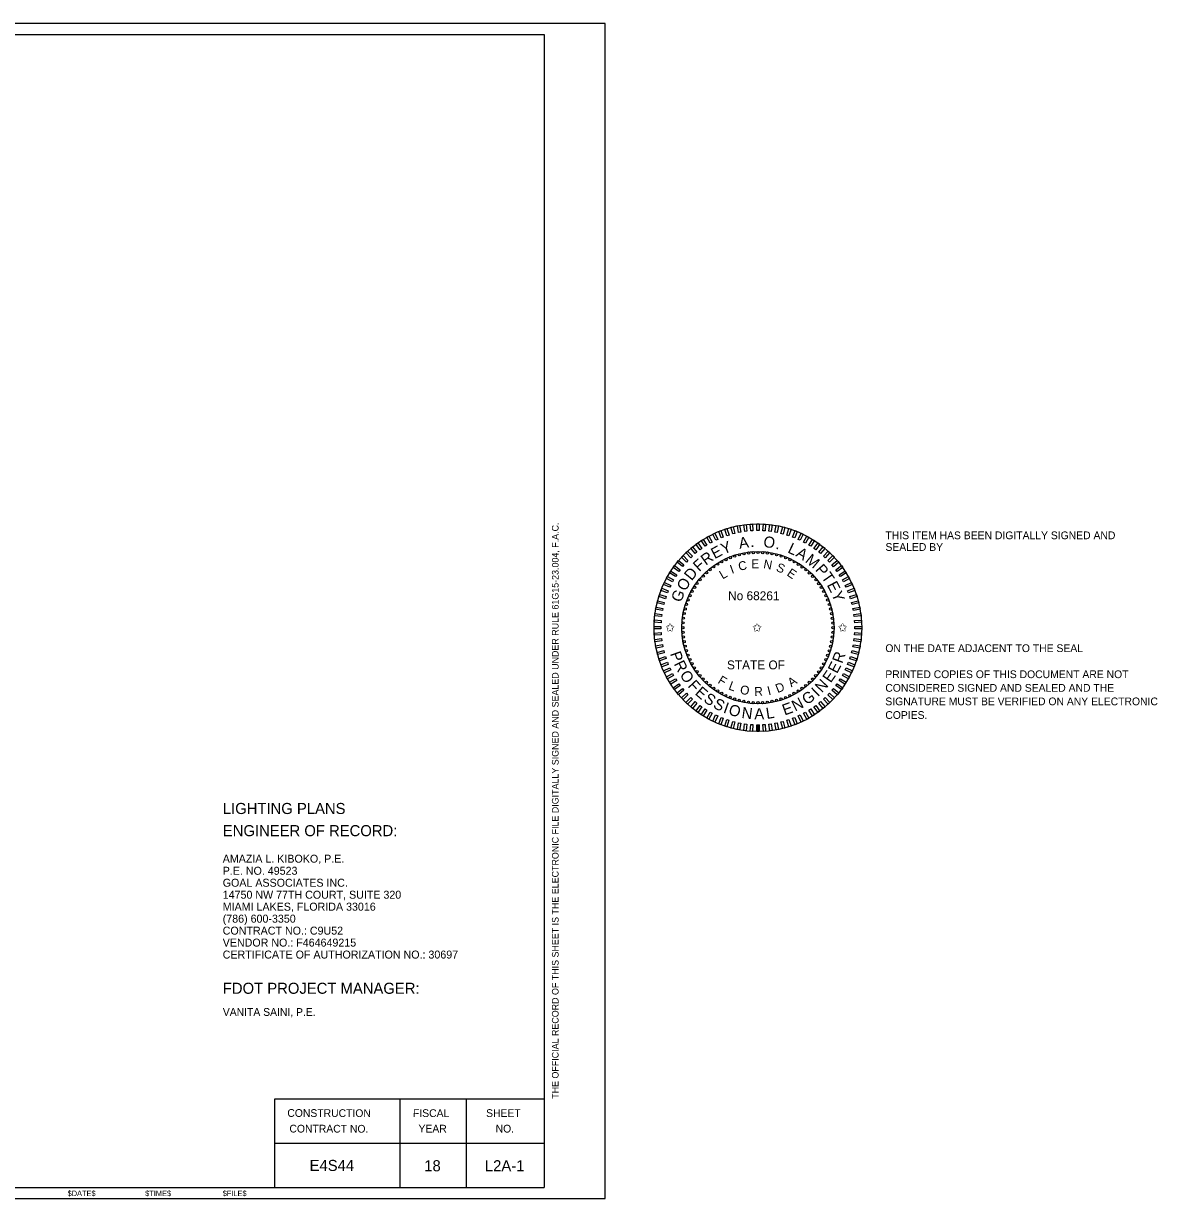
# Model space of a CAD drawing. Extents: x -820.2 to -798.7, y -2201.1 to -2188.5.
# Drawn here: x -808.98 to -798.74, y -2199.12 to -2188.52 of the extents above; entities that cross this region are included whole.
import ezdxf

# ---------------------------------------------------------------- set-up
doc = ezdxf.new("R2010")
doc.units = 0
for name, color, linetype in [('ActivePointCell_dp', 7, 'Continuous'), ('Logo_dp', 7, 'Continuous'), ('NonPlottingEle_dp', 7, 'Continuous'), ('PlotBorder_dp', 7, 'Continuous'), ('SheetBorder_dp', 7, 'Continuous'), ('SheetLines_dp', 7, 'Continuous'), ('TextLabel', 7, 'Continuous'), ('TextMinor', 7, 'Continuous'), ('TextMisc', 7, 'Continuous'), ('TextNotes', 7, 'Continuous'), ('TextShtNo', 7, 'Continuous')]:
    doc.layers.add(name, color=color, linetype=linetype)

msp = doc.modelspace()

# ---------------------------------------------------------------- linework, layer by layer
at = {"layer": 'ActivePointCell_dp'}
msp.add_line((-804.277, -2188.624), (-804.277, -2188.624), dxfattribs=at)
at = {"layer": 'Logo_dp'}
for p, q in [((-802.358, -2194.911), (-802.358, -2194.849)), ((-802.348, -2194.911), (-802.348, -2194.849)), ((-802.338, -2194.911), (-802.338, -2194.848))]:
    msp.add_line(p, q, dxfattribs=at)
for points in [[(-802.711, -2193.177), (-802.729, -2193.186), (-802.756, -2193.13), (-802.738, -2193.121)], [(-802.66, -2193.156), (-802.679, -2193.164), (-802.702, -2193.106), (-802.683, -2193.098)], [(-802.608, -2193.138), (-802.628, -2193.144), (-802.647, -2193.085), (-802.628, -2193.079)], [(-802.556, -2193.123), (-802.575, -2193.128), (-802.591, -2193.068), (-802.571, -2193.063)], [(-802.502, -2193.112), (-802.522, -2193.116), (-802.533, -2193.055), (-802.513, -2193.051)], [(-802.447, -2193.104), (-802.467, -2193.107), (-802.475, -2193.045), (-802.455, -2193.042)], [(-802.393, -2193.1), (-802.413, -2193.101), (-802.417, -2193.039), (-802.396, -2193.037)], [(-802.338, -2193.098), (-802.358, -2193.098), (-802.358, -2193.036), (-802.338, -2193.036)], [(-802.283, -2193.101), (-802.303, -2193.1), (-802.299, -2193.037), (-802.279, -2193.039)], [(-802.228, -2193.107), (-802.248, -2193.104), (-802.24, -2193.042), (-802.22, -2193.045)], [(-802.174, -2193.116), (-802.194, -2193.112), (-802.182, -2193.051), (-802.162, -2193.055)], [(-802.12, -2193.129), (-802.14, -2193.124), (-802.124, -2193.063), (-802.105, -2193.068)], [(-802.068, -2193.144), (-802.087, -2193.138), (-802.068, -2193.079), (-802.048, -2193.085)], [(-802.016, -2193.164), (-802.035, -2193.156), (-802.012, -2193.098), (-801.993, -2193.106)], [(-801.966, -2193.186), (-801.984, -2193.178), (-801.958, -2193.121), (-801.939, -2193.13)], [(-802.898, -2193.293), (-802.913, -2193.306), (-802.953, -2193.258), (-802.937, -2193.245)], [(-802.854, -2193.26), (-802.87, -2193.271), (-802.907, -2193.221), (-802.891, -2193.209)], [(-802.808, -2193.229), (-802.825, -2193.24), (-802.859, -2193.187), (-802.841, -2193.177)], [(-802.76, -2193.202), (-802.778, -2193.212), (-802.808, -2193.157), (-802.79, -2193.147)], [(-801.917, -2193.212), (-801.935, -2193.202), (-801.905, -2193.147), (-801.887, -2193.157)], [(-801.87, -2193.24), (-801.887, -2193.229), (-801.854, -2193.177), (-801.837, -2193.187)], [(-801.825, -2193.272), (-801.842, -2193.26), (-801.805, -2193.209), (-801.788, -2193.221)], [(-801.782, -2193.306), (-801.798, -2193.293), (-801.758, -2193.245), (-801.742, -2193.258)], [(-802.979, -2193.367), (-802.992, -2193.382), (-803.038, -2193.339), (-803.024, -2193.324)], [(-802.939, -2193.329), (-802.954, -2193.343), (-802.997, -2193.297), (-802.982, -2193.283)], [(-801.741, -2193.343), (-801.756, -2193.329), (-801.713, -2193.283), (-801.699, -2193.297)], [(-801.703, -2193.382), (-801.717, -2193.367), (-801.671, -2193.324), (-801.657, -2193.339)], [(-803.05, -2193.451), (-803.062, -2193.467), (-803.112, -2193.431), (-803.1, -2193.414)], [(-803.015, -2193.408), (-803.028, -2193.423), (-803.076, -2193.384), (-803.064, -2193.368)], [(-801.667, -2193.424), (-801.68, -2193.408), (-801.632, -2193.368), (-801.619, -2193.384)], [(-801.634, -2193.467), (-801.646, -2193.451), (-801.595, -2193.414), (-801.583, -2193.431)], [(-803.11, -2193.543), (-803.119, -2193.561), (-803.174, -2193.531), (-803.164, -2193.513)], [(-803.081, -2193.496), (-803.092, -2193.513), (-803.145, -2193.48), (-803.134, -2193.463)], [(-801.603, -2193.513), (-801.614, -2193.496), (-801.562, -2193.463), (-801.551, -2193.48)], [(-801.576, -2193.561), (-801.586, -2193.543), (-801.531, -2193.513), (-801.521, -2193.531)], [(-803.158, -2193.642), (-803.165, -2193.661), (-803.223, -2193.638), (-803.216, -2193.619)], [(-803.135, -2193.592), (-803.144, -2193.61), (-803.2, -2193.583), (-803.192, -2193.565)], [(-801.552, -2193.61), (-801.56, -2193.592), (-801.504, -2193.565), (-801.495, -2193.584)], [(-801.53, -2193.661), (-801.538, -2193.642), (-801.48, -2193.619), (-801.472, -2193.638)], [(-803.193, -2193.746), (-803.198, -2193.766), (-803.258, -2193.75), (-803.253, -2193.731)], [(-803.177, -2193.693), (-803.183, -2193.713), (-803.242, -2193.693), (-803.236, -2193.674)], [(-801.512, -2193.713), (-801.519, -2193.694), (-801.459, -2193.674), (-801.453, -2193.694)], [(-801.498, -2193.766), (-801.503, -2193.746), (-801.442, -2193.731), (-801.437, -2193.75)], [(-803.215, -2193.854), (-803.217, -2193.874), (-803.279, -2193.866), (-803.277, -2193.846)], [(-803.205, -2193.8), (-803.209, -2193.819), (-803.271, -2193.808), (-803.267, -2193.788)], [(-801.486, -2193.82), (-801.49, -2193.8), (-801.429, -2193.788), (-801.425, -2193.808)], [(-801.478, -2193.874), (-801.481, -2193.854), (-801.419, -2193.846), (-801.416, -2193.866)], [(-803.223, -2193.963), (-803.223, -2193.984), (-803.285, -2193.984), (-803.285, -2193.963)], [(-803.22, -2193.908), (-803.222, -2193.929), (-803.284, -2193.925), (-803.283, -2193.904)], [(-801.474, -2193.929), (-801.475, -2193.909), (-801.413, -2193.905), (-801.412, -2193.925)], [(-801.473, -2193.984), (-801.473, -2193.964), (-801.41, -2193.964), (-801.41, -2193.984)], [(-803.222, -2194.018), (-803.22, -2194.038), (-803.283, -2194.042), (-803.284, -2194.022)], [(-803.217, -2194.073), (-803.215, -2194.093), (-803.277, -2194.101), (-803.279, -2194.081)], [(-801.481, -2194.093), (-801.478, -2194.073), (-801.416, -2194.081), (-801.419, -2194.101)], [(-801.475, -2194.039), (-801.474, -2194.018), (-801.412, -2194.022), (-801.413, -2194.043)], [(-803.209, -2194.127), (-803.205, -2194.147), (-803.267, -2194.159), (-803.271, -2194.139)], [(-803.198, -2194.181), (-803.193, -2194.201), (-803.253, -2194.216), (-803.258, -2194.197)], [(-801.503, -2194.201), (-801.498, -2194.181), (-801.437, -2194.197), (-801.442, -2194.217)], [(-801.49, -2194.147), (-801.486, -2194.128), (-801.425, -2194.139), (-801.429, -2194.159)], [(-803.183, -2194.234), (-803.177, -2194.253), (-803.236, -2194.273), (-803.242, -2194.254)], [(-803.165, -2194.286), (-803.158, -2194.305), (-803.216, -2194.328), (-803.223, -2194.309)], [(-801.538, -2194.305), (-801.531, -2194.286), (-801.472, -2194.309), (-801.48, -2194.328)], [(-801.519, -2194.254), (-801.512, -2194.234), (-801.453, -2194.254), (-801.459, -2194.273)], [(-803.144, -2194.337), (-803.135, -2194.355), (-803.192, -2194.382), (-803.2, -2194.363)], [(-803.119, -2194.386), (-803.11, -2194.404), (-803.164, -2194.434), (-803.174, -2194.416)], [(-801.586, -2194.404), (-801.576, -2194.386), (-801.521, -2194.416), (-801.531, -2194.434)], [(-801.56, -2194.355), (-801.552, -2194.337), (-801.495, -2194.364), (-801.504, -2194.382)], [(-803.092, -2194.434), (-803.081, -2194.451), (-803.134, -2194.484), (-803.145, -2194.467)], [(-803.062, -2194.48), (-803.05, -2194.496), (-803.1, -2194.533), (-803.112, -2194.516)], [(-801.646, -2194.496), (-801.634, -2194.48), (-801.583, -2194.516), (-801.595, -2194.533)], [(-801.614, -2194.451), (-801.604, -2194.434), (-801.551, -2194.467), (-801.562, -2194.484)], [(-803.028, -2194.523), (-803.016, -2194.539), (-803.064, -2194.579), (-803.077, -2194.563)], [(-802.993, -2194.565), (-802.979, -2194.58), (-803.024, -2194.623), (-803.038, -2194.608)], [(-802.954, -2194.604), (-802.939, -2194.618), (-802.982, -2194.664), (-802.997, -2194.65)], [(-801.756, -2194.618), (-801.741, -2194.605), (-801.699, -2194.65), (-801.713, -2194.664)], [(-801.717, -2194.58), (-801.703, -2194.565), (-801.658, -2194.608), (-801.671, -2194.623)], [(-801.68, -2194.539), (-801.667, -2194.524), (-801.619, -2194.563), (-801.632, -2194.579)], [(-802.913, -2194.641), (-802.898, -2194.654), (-802.938, -2194.702), (-802.953, -2194.689)], [(-802.87, -2194.675), (-802.854, -2194.687), (-802.891, -2194.738), (-802.907, -2194.726)], [(-802.825, -2194.707), (-802.808, -2194.718), (-802.842, -2194.77), (-802.859, -2194.76)], [(-801.888, -2194.718), (-801.87, -2194.707), (-801.837, -2194.76), (-801.854, -2194.771)], [(-801.842, -2194.687), (-801.825, -2194.676), (-801.789, -2194.726), (-801.805, -2194.738)], [(-801.798, -2194.654), (-801.782, -2194.641), (-801.742, -2194.689), (-801.758, -2194.702)], [(-802.778, -2194.735), (-802.761, -2194.745), (-802.791, -2194.8), (-802.808, -2194.79)], [(-802.73, -2194.761), (-802.711, -2194.77), (-802.738, -2194.826), (-802.756, -2194.817)], [(-802.679, -2194.783), (-802.661, -2194.791), (-802.684, -2194.849), (-802.702, -2194.841)], [(-802.628, -2194.803), (-802.609, -2194.809), (-802.628, -2194.868), (-802.647, -2194.862)], [(-802.575, -2194.819), (-802.556, -2194.824), (-802.571, -2194.884), (-802.591, -2194.879)], [(-802.522, -2194.831), (-802.502, -2194.835), (-802.514, -2194.896), (-802.533, -2194.892)], [(-802.194, -2194.835), (-802.174, -2194.831), (-802.162, -2194.893), (-802.182, -2194.896)], [(-802.14, -2194.824), (-802.12, -2194.819), (-802.105, -2194.879), (-802.124, -2194.884)], [(-802.087, -2194.809), (-802.068, -2194.803), (-802.049, -2194.862), (-802.068, -2194.868)], [(-802.035, -2194.791), (-802.016, -2194.783), (-801.993, -2194.841), (-802.012, -2194.849)], [(-801.984, -2194.77), (-801.966, -2194.761), (-801.94, -2194.818), (-801.958, -2194.826)], [(-801.935, -2194.745), (-801.917, -2194.736), (-801.887, -2194.79), (-801.905, -2194.8)], [(-802.468, -2194.84), (-802.448, -2194.843), (-802.455, -2194.905), (-802.475, -2194.902)], [(-802.413, -2194.846), (-802.393, -2194.847), (-802.397, -2194.91), (-802.417, -2194.909)], [(-802.358, -2194.849), (-802.338, -2194.849), (-802.338, -2194.911), (-802.358, -2194.911)], [(-802.303, -2194.847), (-802.283, -2194.846), (-802.279, -2194.909), (-802.299, -2194.91)], [(-802.248, -2194.843), (-802.228, -2194.84), (-802.22, -2194.902), (-802.24, -2194.905)]]:
    msp.add_lwpolyline(points, close=True, dxfattribs=at)
for centre in [(-802.636, -2193.36), (-802.597, -2193.343), (-802.557, -2193.329), (-802.516, -2193.317), (-802.474, -2193.308), (-802.432, -2193.301), (-802.39, -2193.297), (-802.347, -2193.296), (-802.305, -2193.297), (-802.262, -2193.301), (-802.22, -2193.308), (-802.179, -2193.317), (-802.138, -2193.329), (-802.098, -2193.344), (-802.059, -2193.361), (-802.779, -2193.451), (-802.746, -2193.425), (-802.71, -2193.401), (-802.674, -2193.38), (-802.021, -2193.38), (-801.984, -2193.402), (-801.949, -2193.426), (-801.915, -2193.452), (-802.869, -2193.541), (-802.841, -2193.509), (-802.811, -2193.479), (-801.884, -2193.48), (-801.854, -2193.51), (-801.825, -2193.542), (-802.941, -2193.647), (-802.919, -2193.61), (-802.896, -2193.575), (-801.799, -2193.576), (-801.775, -2193.611), (-801.754, -2193.648), (-802.992, -2193.764), (-802.977, -2193.724), (-802.961, -2193.685), (-801.735, -2193.686), (-801.718, -2193.725), (-801.703, -2193.765), (-803.02, -2193.888), (-803.013, -2193.846), (-803.004, -2193.805), (-801.691, -2193.806), (-801.682, -2193.847), (-801.676, -2193.889), (-803.025, -2193.973), (-803.024, -2193.93), (-801.672, -2193.932), (-801.67, -2193.974), (-803.024, -2194.016), (-803.02, -2194.058), (-803.013, -2194.1), (-801.682, -2194.101), (-801.676, -2194.059), (-801.672, -2194.017), (-803.004, -2194.141), (-802.992, -2194.182), (-801.704, -2194.183), (-801.692, -2194.143), (-802.978, -2194.222), (-802.961, -2194.261), (-802.942, -2194.299), (-801.754, -2194.3), (-801.735, -2194.262), (-801.718, -2194.223), (-802.92, -2194.336), (-802.896, -2194.371), (-802.87, -2194.405), (-801.826, -2194.406), (-801.8, -2194.372), (-801.776, -2194.337), (-802.842, -2194.437), (-802.812, -2194.467), (-802.78, -2194.495), (-802.746, -2194.521), (-801.95, -2194.522), (-801.916, -2194.496), (-801.884, -2194.468), (-801.854, -2194.438), (-802.711, -2194.545), (-802.675, -2194.567), (-802.637, -2194.586), (-802.598, -2194.603), (-802.558, -2194.618), (-802.517, -2194.63), (-802.18, -2194.63), (-802.139, -2194.618), (-802.099, -2194.604), (-802.06, -2194.587), (-802.022, -2194.567), (-801.985, -2194.546), (-802.475, -2194.639), (-802.433, -2194.646), (-802.391, -2194.65), (-802.348, -2194.651), (-802.306, -2194.65), (-802.263, -2194.646), (-802.221, -2194.639)]:
    msp.add_circle(centre, 0.01, dxfattribs=at)
at = {"layer": 'NonPlottingEle_dp'}
for radius in [0.937, 0.687]:
    msp.add_circle((-802.348, -2193.974), radius, dxfattribs=at)
at = {"layer": 'PlotBorder_dp'}
msp.add_lwpolyline([(-820.227, -2199.124), (-803.727, -2199.124), (-803.727, -2188.524), (-820.227, -2188.524)], close=True, dxfattribs=at)
at = {"layer": 'SheetBorder_dp'}
for p, q in [((-819.677, -2188.624), (-804.277, -2188.624)), ((-804.277, -2188.624), (-804.277, -2199.024)), ((-819.677, -2199.024), (-804.277, -2199.024))]:
    msp.add_line(p, q, dxfattribs=at)
at = {"layer": 'SheetLines_dp'}
for p, q in [((-806.708, -2198.224), (-804.277, -2198.224)), ((-806.708, -2199.024), (-806.708, -2198.224)), ((-805.577, -2199.024), (-805.577, -2198.224)), ((-804.977, -2199.024), (-804.977, -2198.224)), ((-806.708, -2198.624), (-804.277, -2198.624))]:
    msp.add_line(p, q, dxfattribs=at)

# ---------------------------------------------------------------- texts
at = {"layer": 'Logo_dp'}
for s, height, rotation, p in [('E', 0.1, 28.1055, (-802.738, -2193.357)), ('Y', 0.1, 21.0633, (-802.66, -2193.314)), ('A', 0.1, 8.8088, (-802.513, -2193.263)), ('.', 0.1, 1.0418, (-802.415, -2193.247)), ('O', 0.1, 352.1877, (-802.303, -2193.245)), ('L', 0.1, 334.6727, (-802.086, -2193.293)), ('F', 0.1, 42.3772, (-802.878, -2193.473)), ('R', 0.1, 35.9269, (-802.818, -2193.416)), ('.', 0.1, 343.5268, (-802.193, -2193.261)), ('A', 0.1, 328.4096, (-802.013, -2193.325)), ('M', 0.1, 320.6426, (-801.928, -2193.377)), ('D', 0.1, 50.8569, (-802.946, -2193.556)), ('I', 0.08, 20.0117, (-802.583, -2193.489)), ('C', 0.08, 12.2025, (-802.516, -2193.462)), ('E', 0.08, 0.4186, (-802.407, -2193.438)), ('N', 0.08, 349.2914, (-802.303, -2193.437)), ('S', 0.08, 337.0221, (-802.19, -2193.459)), ('E', 0.08, 325.8663, (-802.093, -2193.499)), ('P', 0.1, 311.1966, (-801.836, -2193.454)), ('O', 0.1, 59.5178, (-803.002, -2193.651)), ('L', 0.08, 30.4021, (-802.667, -2193.54)), ('T', 0.1, 304.4563, (-801.779, -2193.517)), ('E', 0.1, 297.6315, (-801.728, -2193.588)), ('G', 0.1, 68.0518, (-803.043, -2193.752)), ('Y', 0.1, 290.5893, (-801.686, -2193.667)), ('P', 0.1, 289.4055, (-803.142, -2194.208)), ('R', 0.1, 69.5134, (-801.588, -2194.303)), ('R', 0.1, 296.1458, (-803.109, -2194.3)), ('E', 0.1, 62.4712, (-801.634, -2194.394)), ('O', 0.1, 303.9671, (-803.058, -2194.4)), ('F', 0.08, 328.7241, (-802.716, -2194.47)), ('E', 0.1, 55.4289, (-801.691, -2194.478)), ('F', 0.1, 312.628, (-802.986, -2194.502)), ('E', 0.1, 319.0783, (-802.922, -2194.571)), ('L', 0.08, 339.2916, (-802.619, -2194.529)), ('O', 0.08, 349.6821, (-802.514, -2194.569)), ('R', 0.08, 2.3398, (-802.379, -2194.591)), ('I', 0.08, 14.2037, (-802.252, -2194.584)), ('D', 0.08, 22.0128, (-802.17, -2194.565)), ('A', 0.08, 34.4992, (-802.046, -2194.513)), ('I', 0.1, 43.6456, (-801.808, -2194.602)), ('N', 0.1, 47.1788, (-801.77, -2194.567)), ('S', 0.1, 326.1206, (-802.845, -2194.637)), ('S', 0.1, 333.193, (-802.759, -2194.693)), ('N', 0.1, 26.8614, (-802.012, -2194.731)), ('G', 0.1, 35.1115, (-801.907, -2194.675)), ('I', 0.1, 340.2654, (-802.667, -2194.738)), ('O', 0.1, 343.7986, (-802.62, -2194.756)), ('N', 0.1, 352.4595, (-802.499, -2194.788)), ('A', 0.1, 0.7097, (-802.38, -2194.801)), ('L', 0.1, 8.4767, (-802.268, -2194.798)), ('E', 0.1, 19.8191, (-802.107, -2194.767))]:
    msp.add_text(s, height=height, rotation=rotation, dxfattribs=at).set_placement(p)
for s, p in [('No 68261', (-802.617, -2193.726)), ('✩', (-803.183, -2194.011)), ('✩', (-802.398, -2194.011)), ('✩', (-801.626, -2194.011)), ('STATE OF', (-802.627, -2194.35))]:
    msp.add_text(s, height=0.08, dxfattribs=at).set_placement(p)
at = {"layer": 'TextLabel'}
for s, height, p in [('LIGHTING PLANS', 0.1, (-807.177, -2195.655)), ('ENGINEER OF RECORD:', 0.1, (-807.177, -2195.855)), ('AMAZIA L. KIBOKO, P.E.', 0.07202, (-807.178, -2196.094)), ('P.E. NO. 49523', 0.07202, (-807.178, -2196.203)), ('GOAL ASSOCIATES INC. ', 0.07202, (-807.178, -2196.311)), ('14750 NW 77TH COURT, SUITE 320', 0.07202, (-807.178, -2196.419)), ('MIAMI LAKES, FLORIDA 33016', 0.07202, (-807.178, -2196.527)), ('(786) 600-3350', 0.07202, (-807.178, -2196.635)), ('CONTRACT NO.: C9U52', 0.07202, (-807.178, -2196.743)), ('VENDOR NO.: F464649215', 0.07202, (-807.178, -2196.851)), ('CERTIFICATE OF AUTHORIZATION NO.: 30697', 0.07202, (-807.178, -2196.959)), ('E4S44', 0.1, (-806.394, -2198.875))]:
    msp.add_text(s, height=height, dxfattribs=at).set_placement(p)
at = {"layer": 'TextMinor'}
for s, p in [('$DATE$', (-808.578, -2199.102)), ('$TIME$', (-807.878, -2199.102)), ('$FILE$', (-807.178, -2199.102))]:
    msp.add_text(s, height=0.05, rotation=360, dxfattribs=at).set_placement(p)
at = {"layer": 'TextMisc'}
msp.add_text('THE OFFICIAL RECORD OF THIS SHEET IS THE ELECTRONIC FILE DIGITALLY SIGNED AND SEALED UNDER RULE 61G15-23.004, F.A.C.', height=0.06, rotation=90, dxfattribs=at).set_placement((-804.147, -2198.224))
for s, p in [('THIS ITEM HAS BEEN DIGITALLY SIGNED AND ', (-801.197, -2193.176)), ('SEALED BY', (-801.197, -2193.281)), ('ON THE DATE ADJACENT TO THE SEAL', (-801.198, -2194.194)), ('PRINTED COPIES OF THIS DOCUMENT ARE NOT ', (-801.198, -2194.429)), ('CONSIDERED SIGNED AND SEALED AND THE ', (-801.198, -2194.552)), ('SIGNATURE MUST BE VERIFIED ON ANY ELECTRONIC ', (-801.198, -2194.674)), ('COPIES.', (-801.198, -2194.797))]:
    msp.add_text(s, height=0.07, dxfattribs=at).set_placement(p)
at = {"layer": 'TextNotes'}
for s, height, p in [('FDOT PROJECT MANAGER:', 0.1, (-807.177, -2197.277)), ('VANITA SAINI, P.E.', 0.07, (-807.177, -2197.476))]:
    msp.add_text(s, height=height, dxfattribs=at).set_placement(p)
for s, p in [('CONSTRUCTION', (-806.595, -2198.387)), ('FISCAL', (-805.461, -2198.388)), ('SHEET', (-804.801, -2198.388)), ('CONTRACT NO.', (-806.576, -2198.528)), ('YEAR', (-805.411, -2198.528)), ('NO.', (-804.715, -2198.528))]:
    msp.add_text(s, height=0.07, rotation=359.8607, dxfattribs=at).set_placement(p)
at = {"layer": 'TextShtNo'}
for s, p in [('18', (-805.359, -2198.878)), ('L2A-1', (-804.812, -2198.878))]:
    msp.add_text(s, height=0.1, dxfattribs=at).set_placement(p)

doc.saveas('drawing.dxf')
